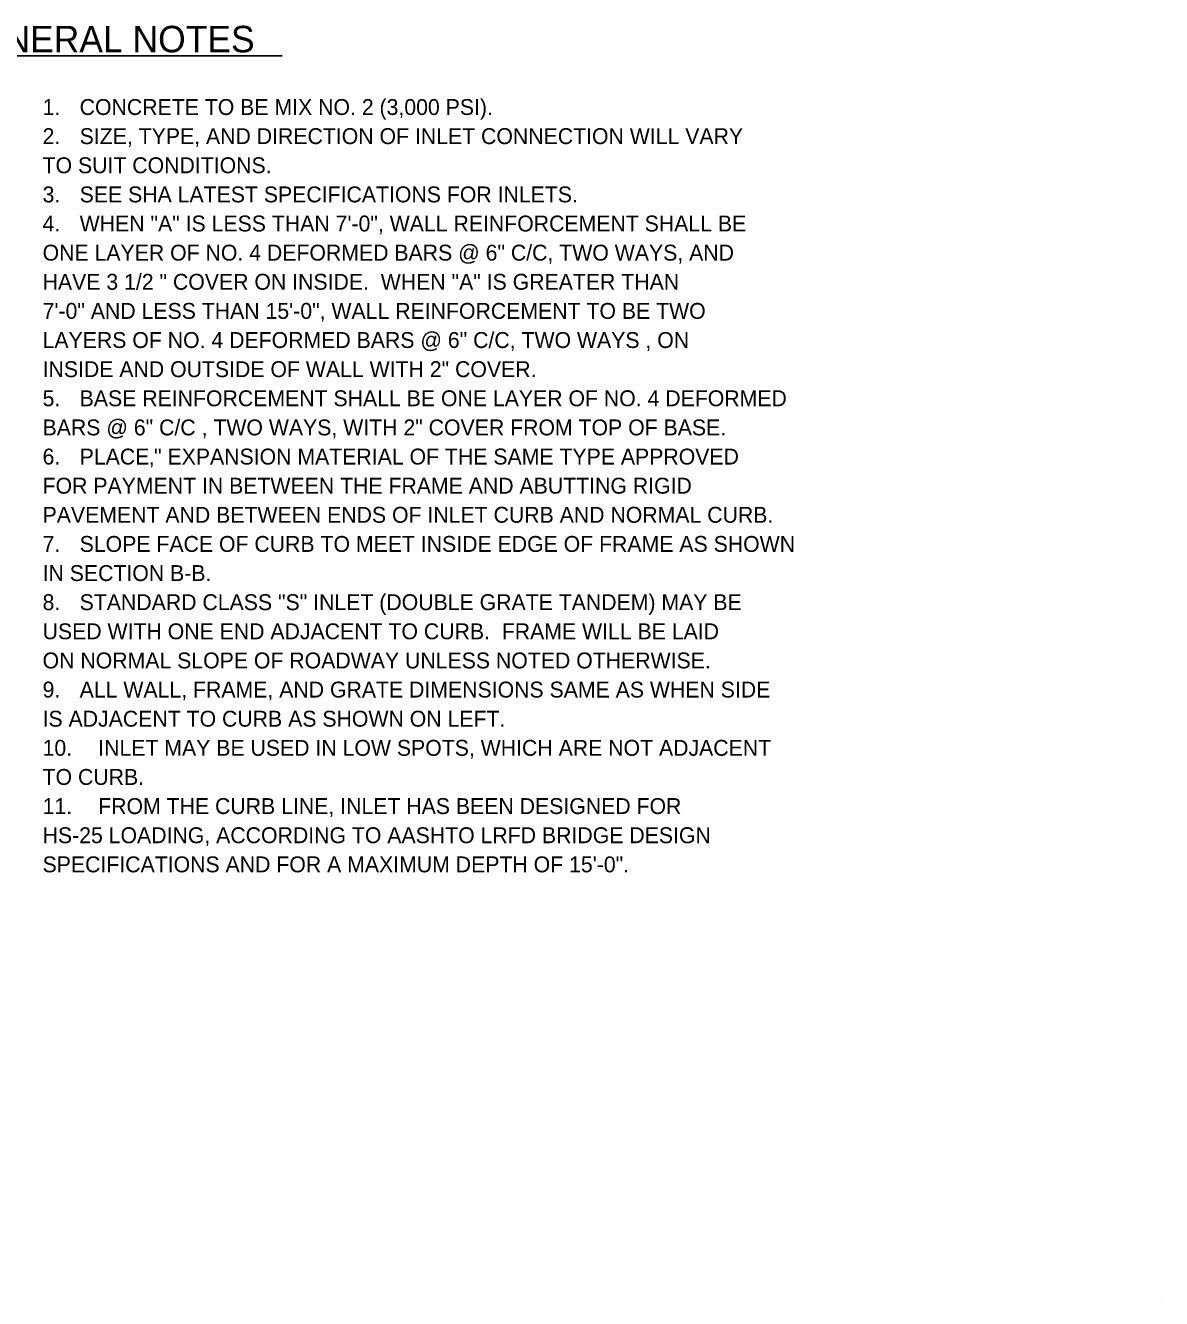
# Model space of a CAD drawing. Extents: x 6.91 to 13.84, y 0.35 to 9.99.
# Drawn here: x 9.548 to 13.838, y 0.349 to 5.155 of the extents above; entities that cross this region are included whole.
import ezdxf

# ---------------------------------------------------------------- set-up
doc = ezdxf.new("R2010")
doc.units = 0
doc.layers.add('DETL-NOTE', color=7, linetype='Continuous')
doc.layers.add('TTLB-TEXT', color=7, linetype='Continuous')

msp = doc.modelspace()

# ---------------------------------------------------------------- linework, layer by layer
at = {"layer": 'DETL-NOTE'}
msp.add_line((9.2669, 5.0407), (10.5175, 5.0407), dxfattribs=at)
at = {"layer": 'TTLB-TEXT'}
msp.add_line((13.838, 0.3486), (13.838, 0.3486), dxfattribs=at)

# ---------------------------------------------------------------- texts
at = {"layer": 'DETL-NOTE'}
for s, height, p in [('GENERAL NOTES', 0.100117, (9.2751, 5.0534)), ('1.', 0.06, (9.6125, 4.817)), ('CONCRETE TO BE MIX NO. 2 (3,000 PSI).', 0.06, (9.7525, 4.817)), ('2.', 0.06, (9.6125, 4.7071)), ('SIZE, TYPE, AND DIRECTION OF INLET CONNECTION WILL VARY', 0.06, (9.7525, 4.7071)), ('TO SUIT CONDITIONS.', 0.06, (9.6125, 4.5971)), ('3.', 0.06, (9.6125, 4.4871)), ('SEE SHA LATEST SPECIFICATIONS FOR INLETS.', 0.06, (9.7525, 4.4871)), ('4.', 0.06, (9.6125, 4.3772)), ('WHEN "A" IS LESS THAN 7\'-0", WALL REINFORCEMENT SHALL BE', 0.06, (9.7525, 4.3772)), ('ONE LAYER OF NO. 4 DEFORMED BARS @ 6" C/C, TWO WAYS, AND ', 0.06, (9.6125, 4.2672)), ('HAVE 3 1/2 " COVER ON INSIDE.  WHEN "A" IS GREATER THAN ', 0.06, (9.6125, 4.1572)), ('7\'-0" AND LESS THAN 15\'-0", WALL REINFORCEMENT TO BE TWO ', 0.06, (9.6125, 4.0473)), ('LAYERS OF NO. 4 DEFORMED BARS @ 6" C/C, TWO WAYS , ON ', 0.06, (9.6125, 3.9373)), ('INSIDE AND OUTSIDE OF WALL WITH 2" COVER.', 0.06, (9.6125, 3.8273)), ('5.', 0.06, (9.6125, 3.7174)), ('BASE REINFORCEMENT SHALL BE ONE LAYER OF NO. 4 DEFORMED ', 0.06, (9.7525, 3.7174)), ('BARS @ 6" C/C , TWO WAYS, WITH 2" COVER FROM TOP OF BASE.', 0.06, (9.6125, 3.6074)), ('6.', 0.06, (9.6125, 3.4974)), ('PLACE‚" EXPANSION MATERIAL OF THE SAME TYPE APPROVED ', 0.06, (9.7525, 3.4974)), ('FOR PAYMENT IN BETWEEN THE FRAME AND ABUTTING RIGID ', 0.06, (9.6125, 3.3874)), ('PAVEMENT AND BETWEEN ENDS OF INLET CURB AND NORMAL CURB.', 0.06, (9.6125, 3.2775)), ('7.', 0.06, (9.6125, 3.1675)), ('SLOPE FACE OF CURB TO MEET INSIDE EDGE OF FRAME AS SHOWN ', 0.06, (9.7525, 3.1675)), ('IN SECTION B-B.', 0.06, (9.6125, 3.0575)), ('8.', 0.06, (9.6125, 2.9476)), ('STANDARD CLASS "S" INLET (DOUBLE GRATE TANDEM) MAY BE ', 0.06, (9.7525, 2.9476)), ('USED WITH ONE END ADJACENT TO CURB.  FRAME WILL BE LAID ', 0.06, (9.6125, 2.8376)), ('ON NORMAL SLOPE OF ROADWAY UNLESS NOTED OTHERWISE.', 0.06, (9.6125, 2.7276)), ('9.', 0.06, (9.6125, 2.6177)), ('ALL WALL, FRAME, AND GRATE DIMENSIONS SAME AS WHEN SIDE ', 0.06, (9.7525, 2.6177)), ('IS ADJACENT TO CURB AS SHOWN ON LEFT.', 0.06, (9.6125, 2.5077)), ('10.', 0.06, (9.6125, 2.3977)), ('INLET MAY BE USED IN LOW SPOTS, WHICH ARE NOT ADJACENT ', 0.06, (9.8225, 2.3977)), ('TO CURB.', 0.06, (9.6125, 2.2878)), ('11.', 0.06, (9.6125, 2.1778)), ('FROM THE CURB LINE, INLET HAS BEEN DESIGNED FOR ', 0.06, (9.8225, 2.1778)), ('HS-25 LOADING, ACCORDING TO AASHTO LRFD BRIDGE DESIGN ', 0.06, (9.6125, 2.0678)), ('SPECIFICATIONS AND FOR A MAXIMUM DEPTH OF 15\'-0".', 0.06, (9.6125, 1.9578))]:
    msp.add_text(s, height=height, dxfattribs=at).set_placement(p)

doc.saveas('drawing.dxf')
